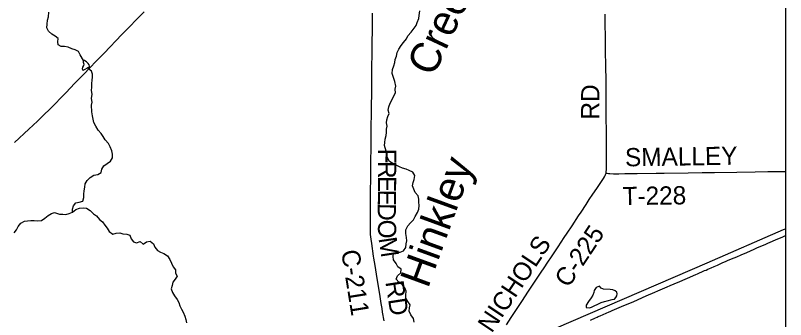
# Model space of a CAD drawing. Extents: x 0 to 34, y 0 to 22.
# Drawn here: x 12.67 to 18.67, y 12.04 to 14.41 of the extents above; entities that cross this region are included whole.
import ezdxf

# ---------------------------------------------------------------- set-up
doc = ezdxf.new("R2010")
doc.units = 0
for name, color, linetype in [('GM_X_County_Road', 7, 'Continuous'), ('GM_X_County_Road_Text', 7, 'Continuous'), ('GM_X_Minor_Lake', 7, 'Continuous'), ('GM_X_Minor_River', 7, 'Continuous'), ('GM_X_Minor_River_Text', 7, 'Continuous'), ('GM_X_Rail_Line', 7, 'Continuous'), ('GM_X_State_Route', 7, 'Continuous'), ('GM_X_Township_Road', 7, 'Continuous'), ('GM_X_Township_Road_Text', 7, 'Continuous'), ('SH_Text', 7, 'Continuous')]:
    doc.layers.add(name, color=color, linetype=linetype)

msp = doc.modelspace()

# ---------------------------------------------------------------- linework, layer by layer
at = {"layer": 'GM_X_County_Road'}
for points in [[(15.5417, 12.0297), (15.5308, 12.0972), (15.5265, 12.1248), (15.5202, 12.1631), (15.5088, 12.2382), (15.4918, 12.3441), (15.484, 12.393), (15.4724, 12.4615), (15.4678, 12.4889), (15.4631, 12.5181), (15.4608, 12.5334), (15.4454, 12.6324), (15.4409, 12.6662), (15.4389, 12.6831), (15.437, 12.7016), (15.4357, 12.7217), (15.4352, 12.7326), (15.4349, 12.7544), (15.4349, 12.826), (15.4356, 12.8897), (15.4359, 12.9316), (15.4354, 12.9673), (15.4364, 13.0248), (15.4376, 13.1538), (15.4382, 13.1957), (15.4389, 13.247), (15.4397, 13.3029), (15.4402, 13.3495), (15.4407, 13.3759), (15.4409, 13.4209), (15.442, 13.48), (15.442, 13.5358), (15.4444, 13.6506), (15.4446, 13.6925), (15.4452, 13.7236), (15.4459, 13.7825), (15.4465, 13.8476), (15.4466, 13.8865), (15.4471, 13.9501), (15.4475, 13.9857), (15.4478, 14.0462), (15.4482, 14.068), (15.4485, 14.1192), (15.449, 14.1798), (15.4513, 14.3131), (15.4512, 14.3501), (15.4524, 14.4268)], [(17.2717, 13.1807), (17.2736, 13.1918), (17.2749, 13.2056), (17.2763, 13.2397), (17.2766, 13.2706), (17.2761, 13.3328), (17.276, 13.3686), (17.2752, 13.409), (17.2749, 13.4634), (17.2749, 13.496), (17.2738, 13.6203), (17.2736, 13.656), (17.2732, 13.7103), (17.2732, 13.7538), (17.2732, 13.8066), (17.2729, 13.8453), (17.2718, 13.9166), (17.2705, 13.9972), (17.2699, 14.0375), (17.2686, 14.1104), (17.2674, 14.1816), (17.267, 14.2373), (17.2668, 14.2575), (17.2662, 14.3241), (17.2662, 14.3722), (17.2658, 14.4187)], [(16.4953, 11.9985), (16.5327, 12.0557), (16.5524, 12.0855), (16.5832, 12.1323), (16.6153, 12.18), (16.6688, 12.2601), (16.7254, 12.3456), (16.7671, 12.4075), (16.7906, 12.4422), (16.8181, 12.4854), (16.8467, 12.5281), (16.8985, 12.6054), (16.9465, 12.6779), (16.9699, 12.7127), (17.0067, 12.7702), (17.0583, 12.8479), (17.0772, 12.8764), (17.1168, 12.9358), (17.1415, 12.9735), (17.1699, 13.0162), (17.1997, 13.0598), (17.2519, 13.137), (17.2607, 13.1515), (17.2654, 13.1611), (17.2687, 13.1696), (17.2717, 13.1807)]]:
    msp.add_lwpolyline(points, dxfattribs=at)
at = {"layer": 'GM_X_Minor_Lake'}
for p, q in [((13.1971, 13.9825), (13.2451, 14.0096)), ((17.2799, 12.1853), (17.3205, 12.1952))]:
    msp.add_line(p, q, dxfattribs=at)
for points in [[(13.2451, 14.0096), (13.2469, 14.0134), (13.243, 14.0248), (13.2363, 14.0332), (13.2219, 14.0473), (13.2095, 14.0557), (13.2028, 14.0632), (13.1963, 14.0536), (13.1973, 14.0442), (13.2013, 14.029), (13.1995, 14.0195), (13.1921, 14.0061), (13.1894, 13.9928), (13.1952, 13.9834), (13.1971, 13.9825)], [(17.3205, 12.1952), (17.3366, 12.1992), (17.3488, 12.2107), (17.3552, 12.2241), (17.3579, 12.2384), (17.3549, 12.2516), (17.3434, 12.2619), (17.3244, 12.2703), (17.3045, 12.2729), (17.2524, 12.2751), (17.2343, 12.2844), (17.2218, 12.2985), (17.1945, 12.2877), (17.1805, 12.2657), (17.176, 12.2496), (17.1677, 12.2286), (17.1547, 12.2075), (17.1351, 12.1788), (17.1174, 12.1501), (17.1176, 12.134), (17.1423, 12.1305), (17.1593, 12.1364), (17.1847, 12.149), (17.2026, 12.1568), (17.2337, 12.1714), (17.2591, 12.1793), (17.2799, 12.1853)]]:
    msp.add_lwpolyline(points, dxfattribs=at)
at = {"layer": 'GM_X_Minor_River'}
for points in [[(13.1996, 14.0585), (13.1721, 14.1027), (13.1604, 14.1282), (13.1338, 14.1412), (13.1081, 14.1476), (13.0796, 14.1615), (13.0521, 14.1659), (13.0265, 14.1675), (13.0027, 14.1796), (13.0005, 14.2033), (13.0031, 14.2299), (12.9792, 14.2476), (12.9516, 14.2635), (12.9276, 14.2869), (12.9141, 14.3114), (12.9166, 14.3419), (12.9191, 14.3732), (12.9254, 14.398), (12.9288, 14.435)], [(15.6561, 14.1468), (15.6747, 14.1736), (15.6944, 14.1976), (15.7158, 14.2254), (15.7279, 14.2511), (15.7522, 14.278), (15.7914, 14.3297), (15.7996, 14.3536), (15.8135, 14.3841), (15.8151, 14.4088), (15.8204, 14.4459)], [(15.7753, 12.0197), (15.7703, 12.0472), (15.7501, 12.0764), (15.7365, 12.1037), (15.7391, 12.1294), (15.7445, 12.1551), (15.7281, 12.1805), (15.7127, 12.205), (15.7124, 12.2297), (15.713, 12.2601), (15.7042, 12.2856), (15.6821, 12.312), (15.6573, 12.3307), (15.6372, 12.3551), (15.6473, 12.3799), (15.6717, 12.403), (15.6742, 12.4324), (15.6503, 12.4502), (15.6368, 12.4747), (15.6166, 12.5049), (15.6125, 12.5305), (15.615, 12.5571), (15.6405, 12.5631), (15.6661, 12.5634), (15.6934, 12.5751), (15.7121, 12.6), (15.7146, 12.6285), (15.7191, 12.6523), (15.7178, 12.6788), (15.7108, 12.711), (15.7124, 12.7395), (15.7263, 12.7682), (15.7488, 12.7922), (15.7712, 12.8171), (15.7851, 12.8429), (15.8018, 12.8725), (15.8129, 12.9002), (15.8145, 12.9268), (15.8123, 12.9534), (15.812, 12.9771), (15.807, 13.0027), (15.784, 13.029), (15.7733, 13.0564), (15.7645, 13.081), (15.7689, 13.1076), (15.7772, 13.1314), (15.7806, 13.1618), (15.7652, 13.1883), (15.7386, 13.2003), (15.7129, 13.2114), (15.6853, 13.2177), (15.6615, 13.2288), (15.6358, 13.2428), (15.6092, 13.2548), (15.5834, 13.2716), (15.568, 13.2999), (15.5639, 13.3255), (15.5589, 13.352), (15.5451, 13.3955), (15.5487, 13.4193), (15.5493, 13.4449), (15.5594, 13.4726), (15.5601, 13.4963), (15.5598, 13.5229), (15.5652, 13.5467), (15.5602, 13.5713), (15.5647, 13.5961), (15.572, 13.6208), (15.5812, 13.6456), (15.5743, 13.6702), (15.5787, 13.6969), (15.5898, 13.7255), (15.6056, 13.7532), (15.6157, 13.777), (15.6305, 13.8057), (15.6293, 13.8351), (15.6347, 13.8589), (15.6267, 13.893), (15.616, 13.9252), (15.6061, 13.9564), (15.6077, 13.9877), (15.6187, 14.0163), (15.6251, 14.043), (15.6295, 14.0668), (15.6378, 14.0915), (15.645, 14.1192), (15.6561, 14.1468)], [(13.1147, 12.8754), (13.1135, 12.8992), (13.1217, 12.9249), (13.1404, 12.9488), (13.1649, 12.9539), (13.1942, 12.9618), (13.2015, 12.9894), (13.2021, 13.0151), (13.2037, 13.0426), (13.21, 13.0702), (13.2116, 13.0959), (13.2274, 13.1236), (13.2518, 13.1457), (13.279, 13.165), (13.3112, 13.1682), (13.3366, 13.1856), (13.341, 13.2123), (13.3568, 13.2371), (13.3841, 13.2555), (13.4095, 13.2729), (13.4262, 13.2997), (13.4259, 13.3272), (13.419, 13.3537), (13.4082, 13.3858), (13.3947, 13.4104), (13.3688, 13.4385), (13.3515, 13.4649), (13.336, 13.4894), (13.3149, 13.5148), (13.2957, 13.545), (13.2802, 13.5752), (13.2742, 13.6017), (13.2692, 13.6273), (13.2632, 13.6585), (13.2626, 13.7088), (13.2661, 13.7326), (13.263, 13.762), (13.2664, 13.7943), (13.2623, 13.8247), (13.2639, 13.8494), (13.2655, 13.8779), (13.2671, 13.9035), (13.2696, 13.9273), (13.2703, 13.951), (13.2615, 13.9756), (13.2377, 13.9924), (13.2283, 14.0001)], [(12.6601, 12.7154), (12.6769, 12.7393), (12.6898, 12.7632), (12.7113, 12.79), (12.7386, 12.8055), (12.7641, 12.8096), (12.7887, 12.8109), (12.8143, 12.8102), (12.8427, 12.8077), (12.872, 12.8118), (12.8984, 12.8302), (12.9237, 12.8504), (12.9491, 12.8659), (12.9746, 12.8729), (13.0126, 12.861), (13.0382, 12.8594), (13.0619, 12.8568), (13.0864, 12.8666), (13.1147, 12.8754), (13.1391, 12.8966), (13.1673, 12.9083), (13.1967, 12.9106), (13.2223, 12.9071), (13.2518, 12.8884), (13.2767, 12.864), (13.3015, 12.8472), (13.3236, 12.82), (13.3484, 12.8003), (13.3667, 12.7759), (13.385, 12.7504), (13.4004, 12.7259), (13.4271, 12.7054), (13.4545, 12.7114), (13.4819, 12.7155), (13.5066, 12.7082), (13.537, 12.7057), (13.5607, 12.6965), (13.5696, 12.669), (13.5888, 12.6446), (13.6125, 12.6382), (13.6399, 12.6461), (13.6638, 12.6274), (13.6901, 12.6448), (13.7194, 12.6499), (13.7442, 12.6303), (13.7549, 12.6038), (13.776, 12.5775), (13.7999, 12.5635), (13.8265, 12.5534), (13.8532, 12.5356), (13.8715, 12.5083), (13.8851, 12.4781), (13.8986, 12.4507), (13.916, 12.4262), (13.9172, 12.4016), (13.9298, 12.377), (13.9149, 12.3531), (13.8953, 12.3292), (13.8908, 12.3035), (13.8835, 12.2797), (13.8924, 12.2503), (13.9087, 12.2249), (13.9289, 12.1966), (13.9415, 12.1721), (13.9513, 12.1456), (13.962, 12.1201), (13.9755, 12.0956), (13.9891, 12.0663), (13.9979, 12.0399), (14.0029, 12.0133)]]:
    msp.add_lwpolyline(points, dxfattribs=at)
at = {"layer": 'GM_X_Rail_Line'}
msp.add_lwpolyline([(16.8851, 11.9739), (18.0589, 12.4824), (18.6549, 12.7402), (18.6712, 12.7473)], dxfattribs=at)
at = {"layer": 'GM_X_State_Route'}
msp.add_lwpolyline([(12.6608, 13.4192), (12.7745, 13.523), (12.8406, 13.5843), (12.8887, 13.6307), (12.9404, 13.6824), (13.0615, 13.8059), (13.1325, 13.8799), (13.2006, 13.9496), (13.2518, 14.0025), (13.2962, 14.049), (13.3604, 14.1161), (13.4993, 14.2609), (13.671, 14.4383)], dxfattribs=at)
at = {"layer": 'GM_X_Township_Road'}
for points in [[(17.2717, 13.1807), (17.2817, 13.179), (17.2906, 13.1775), (17.302, 13.1763), (17.3289, 13.1754), (17.3723, 13.1756), (17.4174, 13.1762), (17.4656, 13.1763), (17.5153, 13.177), (17.6613, 13.179), (17.725, 13.1803), (17.913, 13.1834), (18.0201, 13.1853), (18.118, 13.1858), (18.2921, 13.1877), (18.4335, 13.1896), (18.533, 13.1918), (18.6712, 13.194)], [(17.1495, 12.0347), (17.1907, 12.053), (17.2021, 12.058), (17.2105, 12.0619), (17.2261, 12.0688), (17.2957, 12.0995), (17.3042, 12.1031), (17.3185, 12.1092), (17.3385, 12.1176), (17.3571, 12.1255), (17.3912, 12.1405), (17.4872, 12.181), (17.5854, 12.2232), (17.651, 12.2515), (17.6753, 12.2619), (17.7478, 12.2934), (17.7705, 12.3034), (17.8019, 12.3168), (17.846, 12.3361), (17.9472, 12.3801), (17.9586, 12.385), (17.9672, 12.3887), (17.9899, 12.3986), (17.9999, 12.4028), (18.0184, 12.411), (18.0397, 12.4202), (18.0511, 12.4251), (18.0654, 12.4314), (18.0924, 12.4431), (18.1152, 12.453), (18.1393, 12.4635), (18.1549, 12.4702), (18.1833, 12.4828), (18.2018, 12.4908), (18.219, 12.4981), (18.2503, 12.5115), (18.2918, 12.5291), (18.3246, 12.5433), (18.3687, 12.5625), (18.427, 12.5881), (18.4326, 12.5907), (18.4482, 12.5976), (18.4909, 12.6161), (18.5109, 12.6246), (18.5323, 12.6337), (18.5694, 12.6496), (18.5979, 12.6619), (18.6307, 12.6761), (18.6492, 12.6842), (18.6712, 12.6938)]]:
    msp.add_lwpolyline(points, dxfattribs=at)
at = {"layer": 'SH_Text'}
msp.add_lwpolyline([(1.6712, 21.2991), (18.6712, 21.2991), (18.6712, 4.2991), (1.6712, 4.2991)], close=True, dxfattribs=at)

# ---------------------------------------------------------------- texts
at = {"layer": 'GM_X_County_Road_Text'}
for s, height, rotation, p in [('RD', 0.14205, 90, (17.2196, 13.5975)), ('F', 0.142, 269.62936, (15.4959, 13.3712)), ('R', 0.142, 269.62921, (15.4953, 13.2753)), ('E', 0.142, 269.63222, (15.4946, 13.1587)), ('E', 0.142, 269.63142, (15.4939, 13.0524)), ('D', 0.142, 269.6339, (15.4932, 12.9462)), ('O', 0.142, 271.67344, (15.4925, 12.8156)), ('C-225', 0.14205, 56.46101, (16.9794, 12.2803)), ('M', 0.142, 278.51811, (15.4978, 12.6722)), ('NICHOLS', 0.14205, 56.30992, (16.3811, 11.9285)), ('C-211', 0.14205, 279.1148, (15.2066, 12.5722)), ('RD', 0.14205, 278.81959, (15.5516, 12.3323))]:
    msp.add_text(s, height=height, rotation=rotation, dxfattribs=at).set_placement(p)
at = {"layer": 'GM_X_Minor_River_Text'}
for s, rotation, p in [('Creek', 64.97844, (15.9263, 13.924)), ('Hinkley', 69.97847, (15.8837, 12.2751))]:
    msp.add_text(s, height=0.23688, rotation=rotation, dxfattribs=at).set_placement(p)
at = {"layer": 'GM_X_Township_Road_Text'}
for s, rotation, p in [('SMALLEY', 0.86748, (17.4206, 13.2325)), ('T-228', 0.84282, (17.4016, 12.9301))]:
    msp.add_text(s, height=0.14205, rotation=rotation, dxfattribs=at).set_placement(p)

doc.saveas('drawing.dxf')
